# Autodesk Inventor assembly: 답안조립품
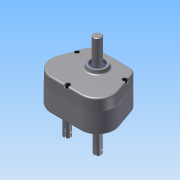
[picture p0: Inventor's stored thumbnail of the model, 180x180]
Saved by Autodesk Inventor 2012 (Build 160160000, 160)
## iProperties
Created: 2014-12
Part Number: 답안조립품
Document SubType Name: Assembly
Designer: Administrator
Author: Administrator
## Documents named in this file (14)
- C:\Documents and Settings\Administrator\바탕 화면\441208V1027\답안조립품.iam
- C:\Documents and Settings\Administrator\바탕 화면\441208V1027\본체.ipt
- C:\Documents and Settings\Administrator\바탕 화면\441208V1027\멈춤링.ipt
- C:\Documents and Settings\Administrator\바탕 화면\441208V1027\메인기어.ipt
- C:\Documents and Settings\Administrator\바탕 화면\441208V1027\메인축.ipt
- C:\Documents and Settings\Administrator\바탕 화면\441208V1027\베어링- 6202.ipt
- C:\Documents and Settings\Administrator\바탕 화면\441208V1027\베어링- 6203.ipt
- C:\Documents and Settings\Administrator\바탕 화면\441208V1027\서브기어.ipt
- C:\Documents and Settings\Administrator\바탕 화면\441208V1027\서브축.ipt
- C:\Documents and Settings\Administrator\바탕 화면\441208V1027\오일시일-D-15.ipt
- C:\Documents and Settings\Administrator\바탕 화면\441208V1027\오일시일-D-17.ipt
- C:\Documents and Settings\Administrator\바탕 화면\441208V1027\커버.ipt
- C:\Documents and Settings\Administrator\바탕 화면\441208V1027\키5x5.ipt
- C:\Documents and Settings\Administrator\바탕 화면\441208V1027\M 5 x 35.ipt
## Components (15 placed, 6 different names)
1. KS B 1336 17 x 1:1
2. KS B 2023 6202 - 15 x 35 x 11:1
3. KS B 2023 6203 - 17 x 40 x 12:1
4. KS B 2804 D D - 15 30 7:1
5. KS B 2804 D D - 17 30 8:1
6. KS B 1003 - 미터 M 5 x 35:1
7. KS B 2023 6202 - 15 x 35 x 11:2
8. KS B 2023 6203 - 17 x 40 x 12:2
9. KS B 2023 6203 - 17 x 40 x 12:3
10. KS B 2023 6203 - 17 x 40 x 12:4
11. KS B 1336 17 x 1:2
12. KS B 1336 17 x 1:3
13. KS B 2804 D D - 15 30 7:2
14. KS B 1003 - 미터 M 5 x 35:2
15. KS B 1003 - 미터 M 5 x 35:3
